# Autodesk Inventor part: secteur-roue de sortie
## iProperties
Created: 2011-07
Part Number: secteur-roue de sortie
Document SubType Name: Modeling
Designer: Laur
Density: 8.47 g/cm^3
Material: Laiton (jaune doux)
Mass: 0.931325 g
Surface Area: 1.9792 cm^2
Volume: 0.109956 cm^3
Author: Laur
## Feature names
1. Extrusion1
